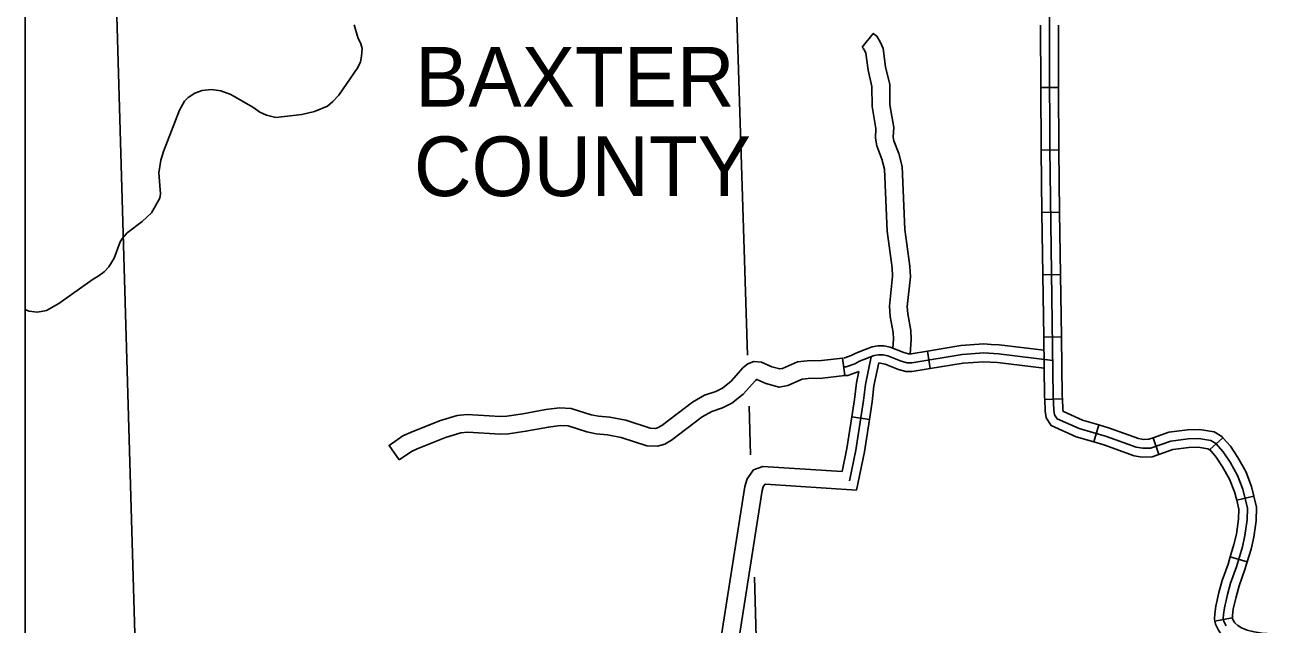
# Model space of a CAD drawing. Extents: x 1377389 to 1380723, y 1168351 to 1170484.
# Drawn here: x 1378340.6 to 1378554.8, y 1169324.4 to 1169425.9 of the extents above; entities that cross this region are included whole.
import ezdxf

# ---------------------------------------------------------------- set-up
doc = ezdxf.new("R2010")
doc.units = 0
for name, color, linetype in [('B_Fill', 7, 'Continuous'), ('B_Text', 7, 'Continuous'), ('Default', 7, 'Continuous')]:
    doc.layers.add(name, color=color, linetype=linetype)

msp = doc.modelspace()

# ---------------------------------------------------------------- linework, layer by layer
at = {"layer": 'B_Fill'}
for p, q in [((1378512.54, 1169415.38), (1378515.54, 1169415.38)), ((1378512.57, 1169404.8), (1378515.57, 1169404.84)), ((1378512.72, 1169394.24), (1378515.72, 1169394.28)), ((1378512.88, 1169383.68), (1378515.88, 1169383.73)), ((1378513.03, 1169373.12), (1378516.03, 1169373.17)), ((1378493.83, 1169367.77), (1378493.33, 1169370.73)), ((1378513.21, 1169362.52), (1378516.2, 1169362.66)), ((1378483.51, 1169359.17), (1378480.55, 1169359.62)), ((1378521.53, 1169355.35), (1378522.38, 1169358.23)), ((1378532.54, 1169353.22), (1378531.54, 1169356.05)), ((1378541.13, 1169354.05), (1378543.37, 1169356.05)), ((1378545.7, 1169345.47), (1378548.61, 1169346.17)), ((1378544.61, 1169335.9), (1378547.48, 1169335.03)), ((1378542.02, 1169325), (1378544.96, 1169325.57))]:
    msp.add_line(p, q, dxfattribs=at)
for points in [[(1378513.96, 1169436.06), (1378514.04, 1169404.99)], [(1378359.16, 1169322.83), (1378356.08, 1169427.5)], [(1378462.88, 1169370.04), (1378461.09, 1169427.33)], [(1378363.24, 1169400.93), (1378363.54, 1169403.07), (1378364, 1169404.57), (1378366.74, 1169411.57), (1378367.56, 1169413.06), (1378368.19, 1169413.73), (1378369.32, 1169414.45), (1378370.57, 1169414.9), (1378372.12, 1169415.06), (1378373.74, 1169414.86), (1378375.4, 1169414.2), (1378379.12, 1169412.07), (1378380.33, 1169411.24), (1378381.45, 1169410.73), (1378383.05, 1169410.29), (1378387.45, 1169410.83), (1378389.56, 1169411.35), (1378391.78, 1169412.22), (1378392.67, 1169413.03), (1378393.68, 1169414.09), (1378396.88, 1169418.81), (1378397.36, 1169419.76), (1378397.55, 1169420.68), (1378397.62, 1169422.02), (1378397.39, 1169422.82), (1378396.92, 1169423.87), (1378396.29, 1169426.03)], [(1378487.64, 1169408.64), (1378486.97, 1169412.45), (1378486.95, 1169415.89), (1378486.25, 1169418.88), (1378485.84, 1169422.01), (1378485.41, 1169423.02), (1378484.75, 1169424.08), (1378484.18, 1169424.55), (1378482.27, 1169422.24)], [(1378512.51, 1169425.94), (1378512.54, 1169415.38)], [(1378515.51, 1169425.94), (1378515.54, 1169415.38)], [(1378484.63, 1169408.44), (1378483.97, 1169412.18), (1378483.95, 1169415.54), (1378483.3, 1169418.34), (1378482.92, 1169421.21), (1378482.74, 1169421.63), (1378482.46, 1169422.08), (1378482.27, 1169422.24)], [(1378512.54, 1169415.38), (1378512.57, 1169404.97), (1378512.57, 1169404.8)], [(1378515.54, 1169415.38), (1378515.57, 1169405), (1378515.57, 1169404.84)], [(1378484.63, 1169408.44), (1378484.55, 1169406.82), (1378484.77, 1169405.54), (1378485.64, 1169403.28), (1378486.09, 1169401.59), (1378486.51, 1169391.08), (1378487.36, 1169384.86), (1378487.44, 1169383.43), (1378486.9, 1169378.33), (1378487.06, 1169376.62), (1378487.56, 1169373.89), (1378487.6, 1169372.75), (1378487.48, 1169371.26)], [(1378487.64, 1169408.64), (1378487.56, 1169407.01), (1378487.68, 1169406.34), (1378488.5, 1169404.2), (1378489.07, 1169402.04), (1378489.5, 1169391.34), (1378490.35, 1169385.15), (1378490.45, 1169383.35), (1378489.92, 1169378.32), (1378490.04, 1169377.03), (1378490.54, 1169374.22), (1378490.61, 1169372.69), (1378490.4, 1169370.24)], [(1378512.57, 1169404.8), (1378512.72, 1169394.24)], [(1378514.04, 1169404.99), (1378514.65, 1169363.07), (1378514.76, 1169360.75), (1378514.88, 1169359.95), (1378515.3, 1169359.28), (1378519.04, 1169357.63), (1378523.67, 1169356.25), (1378528.69, 1169354.45), (1378529.8, 1169354.27), (1378531.11, 1169354.28), (1378534.57, 1169355.5), (1378537.5, 1169355.87), (1378539.29, 1169355.94), (1378541.34, 1169355.61), (1378542.17, 1169355.1), (1378543.43, 1169353.69), (1378544.58, 1169351.9), (1378545.84, 1169349.67), (1378546.76, 1169347.34), (1378547.53, 1169344.13), (1378547.47, 1169342.13), (1378547.08, 1169339.48), (1378546.66, 1169337.6), (1378545.64, 1169334.21), (1378544.66, 1169331.44), (1378544.12, 1169329.5), (1378543.62, 1169327.26), (1378543.47, 1169326.12), (1378543.43, 1169325.43), (1378543.53, 1169324.96), (1378543.89, 1169324.19)], [(1378515.57, 1169404.84), (1378515.72, 1169394.28)], [(1378340.61, 1169377.79), (1378341.19, 1169377.52), (1378342.67, 1169377.34), (1378344.2, 1169377.6), (1378346.31, 1169378.8), (1378351.94, 1169382.79), (1378353.14, 1169383.54), (1378353.94, 1169384.15), (1378354.75, 1169384.99), (1378355.67, 1169386.5), (1378356.67, 1169389.23), (1378357.07, 1169389.9), (1378357.86, 1169390.78), (1378360.38, 1169392.68), (1378361.98, 1169394.19), (1378363.39, 1169396.63), (1378363.5, 1169397.41), (1378363.24, 1169400.93)], [(1378512.72, 1169394.24), (1378512.88, 1169383.68)], [(1378515.72, 1169394.28), (1378515.88, 1169383.73)], [(1378512.88, 1169383.68), (1378513.03, 1169373.12)], [(1378515.88, 1169383.73), (1378516.03, 1169373.17)], [(1378513.03, 1169373.12), (1378513.18, 1169363.02), (1378513.21, 1169362.52)], [(1378516.03, 1169373.17), (1378516.18, 1169363.11), (1378516.2, 1169362.66)], [(1378482.81, 1169371.03), (1378481.21, 1169370.4), (1378480.42, 1169369.98), (1378479.34, 1169369.59), (1378479.19, 1169369.6)], [(1378493.33, 1169370.73), (1378490.59, 1169370.27), (1378490.15, 1169370.29), (1378489.37, 1169370.5), (1378487.05, 1169371.43), (1378485.96, 1169371.65), (1378484.92, 1169371.62), (1378483.96, 1169371.49), (1378482.81, 1169371.03)], [(1378504.16, 1169371.87), (1378502.91, 1169371.96), (1378499.02, 1169371.68), (1378493.33, 1169370.73)], [(1378513.07, 1169370.88), (1378505.49, 1169371.78), (1378504.16, 1169371.87)], [(1378479.33, 1169366.58), (1378478.99, 1169369.56), (1378475.4, 1169369.14), (1378472.96, 1169369.11), (1378471.36, 1169368.95), (1378468.78, 1169367.8), (1378468.34, 1169367.71), (1378467.02, 1169368.08), (1378465.25, 1169368.88), (1378463.94, 1169368.99), (1378462.96, 1169368.57), (1378462.17, 1169367.95), (1378460.1, 1169365.65), (1378458.62, 1169364.48), (1378457.5, 1169363.91), (1378455.62, 1169363.27), (1378453.56, 1169362.09), (1378448.35, 1169358.15), (1378447.65, 1169357.73), (1378447.3, 1169357.63), (1378446.4, 1169357.67), (1378442.27, 1169359.03), (1378439.59, 1169359.56), (1378437.67, 1169359.72), (1378436.43, 1169359.97), (1378433.04, 1169361.03), (1378431.03, 1169361.14), (1378428.71, 1169360.84), (1378424.87, 1169360.11), (1378422.12, 1169359.72), (1378421, 1169359.65), (1378415.44, 1169360.02), (1378413.71, 1169359.83), (1378410.75, 1169358.91), (1378405.81, 1169356.95), (1378404.53, 1169356.37), (1378402.21, 1169354.77), (1378403.91, 1169352.3)], [(1378514.55, 1169369.17), (1378505.35, 1169370.25), (1378502.91, 1169370.43), (1378499.2, 1169370.16), (1378490.68, 1169368.74), (1378489.92, 1169368.78), (1378488.89, 1169369.05), (1378486.61, 1169369.96), (1378485.83, 1169370.12), (1378485.05, 1169370.1), (1378484.35, 1169370), (1378481.85, 1169369.01), (1378481.04, 1169368.58), (1378479.6, 1169368.06), (1378479.16, 1169368.07)], [(1378483.82, 1169369.79), (1378482.84, 1169365.09), (1378482.52, 1169362.36), (1378481.22, 1169353.95), (1378480.15, 1169348.75)], [(1378485.11, 1169368.76), (1378484.29, 1169364.85), (1378483.97, 1169362.16), (1378483.51, 1169359.17)], [(1378493.83, 1169367.77), (1378490.76, 1169367.26), (1378489.69, 1169367.31), (1378488.43, 1169367.65), (1378486.19, 1169368.55), (1378485.11, 1169368.76)], [(1378503.95, 1169368.88), (1378502.91, 1169368.95), (1378499.38, 1169368.7), (1378493.83, 1169367.77)], [(1378513.11, 1169367.86), (1378505.21, 1169368.79), (1378503.95, 1169368.88)], [(1378481.73, 1169367.27), (1378479.84, 1169366.59), (1378479.13, 1169366.6)], [(1378481.73, 1169367.27), (1378481.33, 1169365.34), (1378481, 1169362.56), (1378480.55, 1169359.62)], [(1378479.33, 1169366.58), (1378475.59, 1169366.15), (1378473.13, 1169366.12), (1378472.14, 1169366.01), (1378469.72, 1169364.93), (1378468.25, 1169364.61), (1378465.99, 1169365.26), (1378464.48, 1169365.93), (1378464.46, 1169365.93), (1378464.23, 1169365.76), (1378462.16, 1169363.46), (1378460.25, 1169361.93), (1378458.66, 1169361.14), (1378456.86, 1169360.52), (1378455.22, 1169359.58), (1378450.04, 1169355.66), (1378448.86, 1169354.95), (1378447.66, 1169354.61), (1378445.85, 1169354.69), (1378441.51, 1169356.13), (1378439.17, 1169356.58), (1378437.25, 1169356.75), (1378435.68, 1169357.06), (1378432.5, 1169358.06), (1378431.15, 1169358.13), (1378429.18, 1169357.87), (1378425.36, 1169357.15), (1378422.42, 1169356.73), (1378420.99, 1169356.65), (1378415.51, 1169357.01), (1378414.33, 1169356.88), (1378411.75, 1169356.08), (1378406.98, 1169354.19), (1378406.01, 1169353.75), (1378403.91, 1169352.3)], [(1378513.21, 1169362.52), (1378513.29, 1169360.6), (1378513.47, 1169359.43), (1378514.29, 1169358.12), (1378518.53, 1169356.24), (1378521.53, 1169355.35)], [(1378516.2, 1169362.66), (1378516.28, 1169360.9), (1378516.34, 1169360.49), (1378516.35, 1169360.49), (1378519.57, 1169359.06), (1378522.38, 1169358.23)], [(1378463.4, 1169353.16), (1378463.14, 1169361.4)], [(1378480.55, 1169359.62), (1378479.71, 1169354.22), (1378478.91, 1169350.33)], [(1378483.51, 1169359.17), (1378482.67, 1169353.69), (1378481.33, 1169347.17)], [(1378522.38, 1169358.23), (1378524.15, 1169357.71), (1378529.08, 1169355.94), (1378529.92, 1169355.79), (1378530.84, 1169355.81), (1378531.54, 1169356.05)], [(1378531.54, 1169356.05), (1378534.22, 1169357), (1378537.37, 1169357.39), (1378539.38, 1169357.47), (1378541.88, 1169357.07), (1378543.16, 1169356.28), (1378543.37, 1169356.05)], [(1378543.37, 1169356.05), (1378544.65, 1169354.62), (1378545.88, 1169352.69), (1378547.22, 1169350.33), (1378548.22, 1169347.8), (1378548.61, 1169346.17)], [(1378521.53, 1169355.35), (1378523.21, 1169354.85), (1378528.32, 1169353.02), (1378529.68, 1169352.79), (1378531.37, 1169352.81), (1378532.54, 1169353.22)], [(1378532.54, 1169353.22), (1378534.91, 1169354.06), (1378537.62, 1169354.4), (1378539.2, 1169354.46), (1378540.81, 1169354.21), (1378541.21, 1169353.96)], [(1378541.13, 1169354.05), (1378542.25, 1169352.8), (1378543.31, 1169351.14), (1378544.51, 1169349.04), (1378545.35, 1169346.89), (1378545.7, 1169345.47)], [(1378461.29, 1169321.13), (1378458.33, 1169321.59), (1378462.41, 1169347.8), (1378462.81, 1169349.12), (1378463.92, 1169350.63), (1378465.47, 1169351.2), (1378478.91, 1169350.33)], [(1378461.29, 1169321.13), (1378465.34, 1169347.14), (1378465.53, 1169347.76), (1378465.8, 1169348.13), (1378465.91, 1169348.17), (1378481.33, 1169347.17)], [(1378545.7, 1169345.47), (1378546.05, 1169343.98), (1378546, 1169342.26), (1378545.64, 1169339.74), (1378545.23, 1169337.98), (1378544.61, 1169335.9)], [(1378548.61, 1169346.17), (1378549.06, 1169344.29), (1378548.99, 1169342), (1378548.59, 1169339.2), (1378548.14, 1169337.21), (1378547.48, 1169335.03)], [(1378544.61, 1169335.9), (1378544.24, 1169334.67), (1378543.25, 1169331.88), (1378542.69, 1169329.86), (1378542.17, 1169327.51), (1378542.01, 1169326.25), (1378541.95, 1169325.33), (1378542.02, 1169325)], [(1378547.48, 1169335.03), (1378547.09, 1169333.73), (1378546.12, 1169330.98), (1378545.6, 1169329.13), (1378545.13, 1169327), (1378544.99, 1169325.97), (1378544.97, 1169325.54)], [(1378464.36, 1169322.33), (1378464.05, 1169332.46)], [(1378542.02, 1169325), (1378542.12, 1169324.5), (1378542.61, 1169323.45), (1378543.13, 1169322.69), (1378544.07, 1169321.85), (1378545.13, 1169321.19), (1378546.52, 1169320.61), (1378548.04, 1169320.22), (1378549.71, 1169319.97), (1378552.34, 1169319.79)], [(1378544.96, 1169325.57), (1378544.99, 1169325.43), (1378545.22, 1169324.95), (1378545.39, 1169324.69), (1378545.88, 1169324.26), (1378546.52, 1169323.86), (1378547.47, 1169323.46), (1378548.63, 1169323.17), (1378550.04, 1169322.95), (1378552.54, 1169322.78)]]:
    msp.add_lwpolyline(points, dxfattribs=at)
at = {"layer": 'B_Text'}
msp.add_lwpolyline([(1378340.61, 1169579.43), (1379848.03, 1169579.43), (1379848.03, 1168702.1), (1378340.61, 1168702.1)], close=True, dxfattribs=at)

# ---------------------------------------------------------------- texts
at = {"layer": 'Default'}
for s, p in [('BAXTER', (1378406.62, 1169412.16)), ('COUNTY', (1378406.4, 1169397))]:
    msp.add_text(s, height=10.107, rotation=360, dxfattribs=at).set_placement(p)

doc.saveas('drawing.dxf')
